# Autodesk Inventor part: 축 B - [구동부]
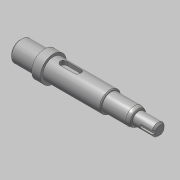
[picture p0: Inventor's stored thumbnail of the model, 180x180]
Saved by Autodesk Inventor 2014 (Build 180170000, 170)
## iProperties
Created: 2020-04
Part Number: 축 B - [구동부]
Material: 강철, 연강
Document SubType Name: Modeling
Designer: mduedu
Density: 7.86 g/cm^3
Appearance: 강철
Mass: 60.8547 g
Surface Area: 31.2855 cm^2
Volume: 7.74232 cm^3
Author: mduedu
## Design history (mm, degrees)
sketch "스케치1"
  geometry: L1 (0, 0)-(14, 0); L2 (14, 0)-(14, 6); L3 (14, 6)-(0, 6); L4 (0, 6)-(0, 0); L5 (14, 0)-(19, 0); L6 (19, 0)-(19, 7.5); L7 (19, 7.5)-(14, 7.5); L8 (14, 7.5)-(14, 0); L9 (19, 0)-(52, 0); L10 (52, 0)-(52, 6); L11 (52, 6)-(19, 6); L12 (19, 6)-(19, 0); L13 (52, 0)-(68, 0); L14 (68, 0)-(68, 5); L15 (68, 5)-(52, 5); L16 (52, 5)-(52, 0); L17 (68, 0)-(80, 0); L18 (80, 0)-(80, 3.5); L19 (80, 3.5)-(68, 3.5); L20 (68, 3.5)-(68, 0)
  constraints: 40 end point, 10 parallel, 5 horizontal, 5 perpendicular
  dimensions: "d0" = 80 distance between parallel lines of L18 L4; "d2" = 14 distance of L2.end L3.end; "d3" = 5 distance of L6.end L7.end; "d5" = 7 diameter of L19 L17; "d6" = 10 diameter of L15 L13; "d7" = 12 diameter of L11 L9; "d8" = 12 diameter of L3 L1; "d9" = 15 diameter of L7 L5; "d35" = 16 distance of L14.end L15.end; "d36" = 52 distance between parallel lines of L10 L4
revolve "회전1" sketch "스케치1" stored, may be unused: angle "d11" = 90 deg
sketch "스케치2"
  geometry: L1 (0, 6)-(0, -6) reference; L2 (0, -6)-(-14, -6) reference; L3 (-14, -6)-(-14, -7.5) reference; L4 (-14, -7.5)-(-19, -7.5) reference; L5 (-19, -7.5)-(-19, -6) reference; L6 (-19, -6)-(-52, -6) reference; L7 (-52, -6)-(-52, -5) reference; L8 (-52, -5)-(-68, -5) reference; L9 (-68, -5)-(-68, -3.5) reference; L10 (-68, -3.5)-(-80, -3.5) reference; L11 (-80, -3.5)-(-80, 3.5) reference; L12 (-80, 3.5)-(-68, 3.5) reference; L13 (-68, 3.5)-(-68, 5) reference; L14 (-68, 5)-(-52, 5) reference; L15 (-52, 5)-(-52, 6) reference; L16 (-52, 6)-(-19, 6) reference; L17 (-19, 6)-(-19, 7.5) reference; L18 (-19, 7.5)-(-14, 7.5) reference; L19 (-14, 7.5)-(-14, 6) reference; L20 (-14, 6)-(0, 6) reference; L21 (-80, 3.5)-(-72, 3.5); L22 (-72, 3.5)-(-72, 2.3); L23 (-72, 2.3)-(-80, 2.3); L24 (-80, 2.3)-(-80, 3.5); 1 further point
  constraints: 8 end point, 2 parallel, 1 horizontal, 1 perpendicular
  dimensions: "d37" = 8 distance of L22.end L23.end; "d38" = 1.2 distance of L21.end L22.end
extrude "돌출1" cut sketch "스케치2" stored distance "d14" = 2; taper "d15" = 0 deg
fillet "모깎기1" dims "d16" = 1
sketch "스케치3"
  geometry: L1 (0, -6)-(0, 6) reference; L2 (0, 6)-(14, 6) reference; L3 (14, 6)-(14, 7.5) reference; L4 (14, 7.5)-(19, 7.5) reference; L5 (19, 7.5)-(19, 6) reference; L6 (19, 6)-(52, 6) reference; L7 (52, 6)-(52, 5) reference; L8 (52, 5)-(68, 5) reference; L9 (68, 5)-(68, 3.5) reference; L10 (68, 3.5)-(80, 3.5) reference; L11 (80, 3.5)-(80, -3.5) reference; L12 (80, -3.5)-(68, -3.5) reference; L13 (68, -3.5)-(68, -5) reference; L14 (68, -5)-(52, -5) reference; L15 (52, -5)-(52, -6) reference; L16 (52, -6)-(19, -6) reference; L17 (19, -6)-(19, -7.5) reference; L18 (19, -7.5)-(14, -7.5) reference; L19 (14, -7.5)-(14, -6) reference; L20 (14, -6)-(0, -6) reference; L21 (23, 6)-(35, 6); L22 (35, 6)-(35, 3.5); L23 (35, 3.5)-(23, 3.5); L24 (23, 3.5)-(23, 6); 1 further point
  constraints: 8 end point, 2 parallel, 1 horizontal, 1 perpendicular, 1 point on line
  dimensions: "d17" = 12 distance of L22.end L23.end; "d18" = 2.5 distance of L21.end L22.end; "d19" = 4 distance from line of L24 L4.end
extrude "돌출2" cut sketch "스케치3" stored distance "d20" = 4; taper "d21" = 0 deg
fillet "모깎기2" dims "d22" = 2
chamfer "모따기1" distance "d23" = 1; stored, may be unused: second distance "d24" = 2, angle "d25" = 45 deg
chamfer "모따기2" distance "d26" = 0.5; stored, may be unused: second distance "d27" = 2, angle "d28" = 45 deg
fillet "모깎기3" dims "d29" = 0.3
chamfer "모따기3" distance "d30" = 1.39; stored, may be unused: second distance "d31" = 2, angle "d32" = 30 deg
fillet "모깎기4" dims "d33" = 4, "d34" = 0.5
node "솔리드1"
node "절단 모서리 투영2"
node "절단 모서리 투영3"
